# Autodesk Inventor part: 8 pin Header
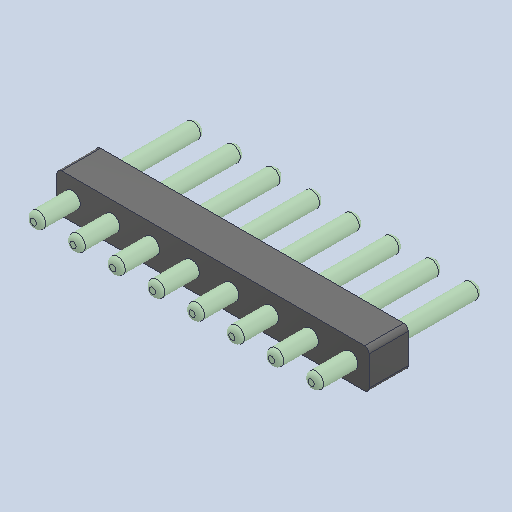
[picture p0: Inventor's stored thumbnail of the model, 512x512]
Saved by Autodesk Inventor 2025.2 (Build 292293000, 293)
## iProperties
Created: 2025-04
Part Number: 8 pin Header
Material: Generic
Description: PART--DESC
Document SubType Name: Modeling
Designer: BennF
Density: 1 g/cm^3
Appearance: Default
Author: BennF
Revision Number: NONE
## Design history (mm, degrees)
feature "Solid"
body "Solid1"
